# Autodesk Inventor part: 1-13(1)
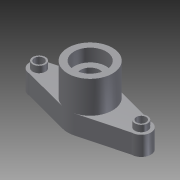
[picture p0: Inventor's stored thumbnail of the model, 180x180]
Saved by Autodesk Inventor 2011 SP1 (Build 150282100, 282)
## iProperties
Created: 2014-02
Part Number: 1-13(1)
Document SubType Name: Modeling
Designer: Administrator
Density: 1 g/cm^3
Author: Administrator
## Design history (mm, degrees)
sketch "草图1"
  geometry: L1 (-16, 3)-(-1.794, 6.766); L2 (-16, -3)-(-1.794, -6.766); L3 (16, 3)-(1.794, 6.766); L4 (16, -3)-(1.794, -6.766); A1 r 3 centre (16, 0) between (16, -3) and (16, 3); A2 r 3 centre (-16, 0) between (-16, 3) and (-16, -3); A3 r 7 centre (0, 0) between (-1.794, -6.766) and (1.794, -6.766); A4 r 7 centre (0, 0) between (1.794, 6.766) and (-1.794, 6.766); 1 further point
  constraints: 8 end point, 8 point on circle, 4 centre point, 4 tangent, 1 coincident
  dimensions: "d3" = 6 diameter of A1; "d4" = 6 diameter of A2
extrude "拉伸1" new body sketch "草图1" distance "d5" = 6; taper "d6" = 0 deg
sketch "草图2"
  geometry: C1 r 7 at (0, 0); A1 r 7 centre (0, 0) between (-1.794, -6.766) and (1.794, -6.766) reference; A2 r 7 centre (0, 0) between (1.794, 6.766) and (-1.794, 6.766) reference
  constraints: 1 centre point, 1 coincident, 1 concentric
extrude "拉伸2" join sketch "草图2" distance "d7" = 10; taper "d8" = 0 deg
sketch "草图3"
  geometry: C1 r 7 at (0, 0) reference; C2 r 5 at (0, 0)
  constraints: 1 centre point, 1 coincident
  dimensions: "d9" = 10 diameter of C2
extrude "拉伸3" cut sketch "草图3" distance "d10" = 4; taper "d11" = 0 deg
sketch "草图4"
  geometry: C1 r 5 at (0, 0) reference; C2 r 3 at (0, 0)
  constraints: 1 centre point, 1 coincident
  dimensions: "d12" = 6 diameter of C2
extrude "拉伸4" cut sketch "草图4" stored distance "d13" = 4; taper "d14" = 0 deg
sketch "草图5"
  geometry: C1 r 2 at (16, 0); A1 r 3 centre (16, 0) between (16, -3) and (16, 3) reference
  constraints: 1 centre point, 1 coincident
  dimensions: "d15" = 4 diameter of C1
extrude "拉伸5" join sketch "草图5" distance "d16" = 2; taper "d17" = 0 deg
sketch "草图6"
  geometry: C1 r 2 at (0, 0) reference; C2 r 1.5 at (0, 0); 1 further point
  constraints: 1 centre point, 1 coincident
  dimensions: "d18" = 3 diameter of C2
extrude "拉伸6" cut sketch "草图6" stored distance "d19" = 2; taper "d20" = 0 deg
mirror "镜像1"
node "实体1"
other parameters: "d0" = 14
